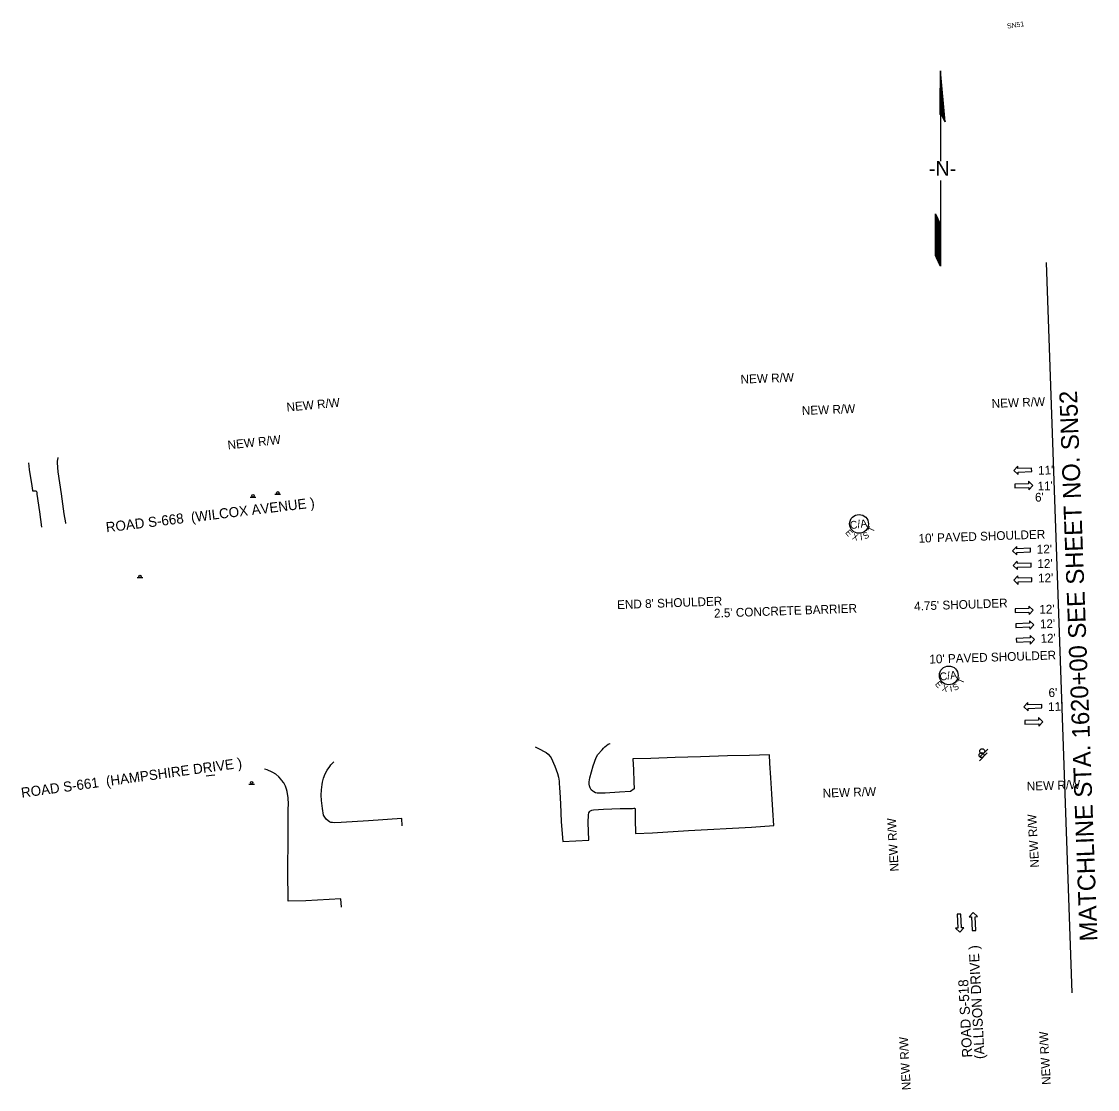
# Model space of a CAD drawing. Extents: x 1807400 to 1809002, y 1189416 to 1190516.
# Drawn here: x 1808144 to 1809002, y 1189664 to 1190516 of the extents above; entities that cross this region are included whole.
import ezdxf

# ---------------------------------------------------------------- set-up
doc = ezdxf.new("R2010")
doc.units = 0
for name, color, linetype in [('RD_EX_Road', 7, 'Continuous'), ('RD_PD_Final_LnLine', 7, 'Continuous'), ('RD_PD_Final_TX', 7, 'Continuous'), ('RD_PD_RW_TX', 7, 'Continuous'), ('RD_SHT_MatchLine', 7, 'Continuous'), ('RD_SHT_TX', 7, 'Continuous'), ('RD_Sketch1', 7, 'Continuous'), ('RD_Sketch8', 7, 'Continuous'), ('RD_TX_RoadID', 7, 'Continuous'), ('SN_P_Signs', 7, 'Continuous')]:
    doc.layers.add(name, color=color, linetype=linetype)

# ---------------------------------------------------------------- blocks, each defined once
blk = doc.blocks.new('SARRW2')
at = {"layer": 'RD_PD_Final_LnLine'}
blk.add_lwpolyline([(-12, 1.2), (-12, -1.2), (-2.83, -1.2), (-2.83, -2.83), (0, 0), (-2.83, 2.83), (-2.83, 1.2)], close=True, dxfattribs=at)

msp = doc.modelspace()

# ---------------------------------------------------------------- linework, layer by layer
at = {"layer": 'RD_EX_Road'}
for points in [[(1808160.15, 1190112.97), (1808158.56, 1190125.05), (1808156.51, 1190139.18), (1808156.33, 1190140.46), (1808156.04, 1190141.13), (1808155.62, 1190141.46), (1808155.39, 1190141.54), (1808154.94, 1190141.57), (1808154.67, 1190141.6), (1808154.21, 1190141.61), (1808153.42, 1190141.63), (1808152.99, 1190141.64), (1808152.87, 1190142.04), (1808152.31, 1190145.84), (1808150.36, 1190159), (1808149.69, 1190164.21)], [(1808179.38, 1190115.85), (1808179.29, 1190116.06), (1808179.19, 1190116.4), (1808177.84, 1190123.51), (1808175.71, 1190139.55), (1808173.13, 1190157.12), (1808172.49, 1190164.12), (1808172.65, 1190165.43), (1808172.72, 1190165.93), (1808172.87, 1190166.46), (1808172.94, 1190166.89), (1808173, 1190167.3), (1808173.04, 1190167.94), (1808173.04, 1190168.58)], [(1808553.71, 1189937.58), (1808558, 1189935.38), (1808560.49, 1189934.01), (1808562.46, 1189932.97), (1808564.21, 1189931.6), (1808565.69, 1189929.95), (1808566.44, 1189928.84), (1808569.35, 1189922.01), (1808570.4, 1189919.27), (1808571.62, 1189916.37), (1808572.46, 1189913.33), (1808572.92, 1189910.22), (1808573, 1189908.63), (1808573.21, 1189904.87), (1808573.55, 1189901.39), (1808573.94, 1189891.93), (1808574.41, 1189877.55), (1808575.84, 1189862.11), (1808596.65, 1189862.96), (1808596.05, 1189877.2), (1808596.3, 1189883.35), (1808596.64, 1189884.9), (1808597.01, 1189885.69), (1808597.37, 1189886.13), (1808597.83, 1189886.46), (1808599.06, 1189886.89), (1808600.37, 1189887.15), (1808608.26, 1189887.7), (1808621.65, 1189888.22), (1808631.53, 1189888.38), (1808632.51, 1189888.46), (1808632.99, 1189888.46), (1808633.39, 1189888.44), (1808633.57, 1189888.4), (1808633.67, 1189888.17), (1808633.46, 1189885.04), (1808633.52, 1189879.82), (1808633.95, 1189868.4), (1808647.46, 1189868.97), (1808676.11, 1189870.63), (1808726.27, 1189873.52), (1808744.3, 1189874.68), (1808743.36, 1189887), (1808742.57, 1189899.94), (1808741.71, 1189912.86), (1808740.98, 1189924.51), (1808740.65, 1189931.23), (1808724.9, 1189930.66), (1808707.17, 1189930.25), (1808685.64, 1189929.62), (1808665.59, 1189928.89), (1808646, 1189928.28), (1808631.8, 1189927.91), (1808632.18, 1189919.1), (1808632.48, 1189909.71), (1808632.66, 1189904.06), (1808629.73, 1189901.77), (1808621.16, 1189901.22), (1808609.52, 1189900.53), (1808604.82, 1189900.54), (1808603.29, 1189900.5), (1808601.79, 1189900.84), (1808600.44, 1189901.56), (1808599.78, 1189902.1), (1808598.54, 1189903.3), (1808597.59, 1189904.76), (1808597, 1189906.39), (1808596.81, 1189907.76), (1808596.84, 1189909.65), (1808597.44, 1189912.73), (1808599.99, 1189922.41), (1808602.47, 1189929.13), (1808603.77, 1189931.43), (1808607.28, 1189935.16), (1808608.28, 1189936.47), (1808609.42, 1189937.66), (1808610.7, 1189938.69), (1808612.09, 1189939.57), (1808613.58, 1189940.28), (1808613.65, 1189940.31)], [(1808447.69, 1189874.41), (1808447.37, 1189880.31), (1808420.81, 1189878.37), (1808398.86, 1189877.26), (1808393.62, 1189877), (1808392.06, 1189877.04), (1808390.72, 1189877.17), (1808389.6, 1189877.6), (1808388.61, 1189878.39), (1808387.09, 1189879.81), (1808385.94, 1189881.29), (1808384.97, 1189883.05), (1808383.96, 1189888.29), (1808383.24, 1189894.79), (1808382.99, 1189899.04), (1808383.14, 1189903.3), (1808383.68, 1189907.53), (1808384, 1189909.22), (1808384.92, 1189912.6), (1808386.2, 1189915.87), (1808387.85, 1189918.97), (1808389.83, 1189921.86), (1808390.83, 1189923.1), (1808392.51, 1189924.99), (1808393.12, 1189925.48)], [(1808298.08, 1189915.01), (1808295.53, 1189914.65), (1808291.36, 1189914.18)], [(1808399.22, 1189809.6), (1808398.8, 1189816.17), (1808370.69, 1189814.73), (1808356.57, 1189814.25), (1808356.49, 1189838.68), (1808356.55, 1189864.58), (1808356.77, 1189877.24), (1808356.79, 1189887.82), (1808356.85, 1189891.81), (1808356.58, 1189896.85), (1808355.91, 1189901.86), (1808355.47, 1189903.63), (1808354.48, 1189906.27), (1808353.12, 1189908.74), (1808351.44, 1189911), (1808351.03, 1189911.56), (1808349.1, 1189913.72), (1808346.9, 1189915.61), (1808344.46, 1189917.17), (1808343.91, 1189917.43), (1808339.95, 1189919.06), (1808337.87, 1189919.7)]]:
    msp.add_lwpolyline(points, dxfattribs=at)
at = {"layer": 'RD_SHT_MatchLine'}
msp.add_line((1808961.42, 1190323.98), (1808981.96, 1189741.27), dxfattribs=at)
at = {"layer": 'RD_Sketch1'}
for p, q in [((1808877.06, 1190477.18), (1808876.85, 1190442.01)), ((1808880.79, 1190436.48), (1808877.06, 1190477.18)), ((1808877.06, 1190442.31), (1808877.06, 1190420.49)), ((1808877.37, 1190443.42), (1808880.79, 1190436.48)), ((1808877.06, 1190420.49), (1808877.06, 1190405.01)), ((1808877.06, 1190389.57), (1808877.06, 1190363.79)), ((1808873.07, 1190348.74), (1808873.07, 1190362.91)), ((1808873.07, 1190362.91), (1808877.06, 1190354.34)), ((1808877.06, 1190363.79), (1808877.06, 1190321.27)), ((1808873.07, 1190329.84), (1808873.07, 1190348.74)), ((1808877.06, 1190321.27), (1808873.07, 1190329.84))]:
    msp.add_line(p, q, dxfattribs=at)
for points in [[(1808877.07, 1190442.62), (1808877.07, 1190477.06)], [(1808877.17, 1190442.88), (1808877.17, 1190476.03)], [(1808877.26, 1190443.14), (1808877.26, 1190474.99)], [(1808877.36, 1190443.4), (1808877.36, 1190473.96)], [(1808877.45, 1190443.24), (1808877.45, 1190472.93)], [(1808877.55, 1190443.05), (1808877.55, 1190471.9)], [(1808877.64, 1190442.86), (1808877.64, 1190470.86)], [(1808877.74, 1190442.67), (1808877.74, 1190469.83)], [(1808877.83, 1190442.48), (1808877.83, 1190468.8)], [(1808877.92, 1190442.29), (1808877.92, 1190467.77)], [(1808878.02, 1190442.09), (1808878.02, 1190466.73)], [(1808878.11, 1190441.9), (1808878.11, 1190465.7)], [(1808878.21, 1190441.71), (1808878.21, 1190464.67)], [(1808876.98, 1190442.36), (1808876.98, 1190463.14)], [(1808878.3, 1190441.52), (1808878.3, 1190463.64)], [(1808878.4, 1190441.33), (1808878.4, 1190462.6)], [(1808878.49, 1190441.14), (1808878.49, 1190461.57)], [(1808878.59, 1190440.94), (1808878.59, 1190460.54)], [(1808878.68, 1190440.75), (1808878.68, 1190459.51)], [(1808878.77, 1190440.56), (1808878.77, 1190458.47)], [(1808878.87, 1190440.37), (1808878.87, 1190457.44)], [(1808878.96, 1190440.18), (1808878.96, 1190456.41)], [(1808879.06, 1190439.99), (1808879.06, 1190455.38)], [(1808876.88, 1190442.1), (1808876.88, 1190447.24)], [(1808879.15, 1190439.79), (1808879.15, 1190454.34)], [(1808879.25, 1190439.6), (1808879.25, 1190453.31)], [(1808879.34, 1190439.41), (1808879.34, 1190452.28)], [(1808879.44, 1190439.22), (1808879.44, 1190451.25)], [(1808879.53, 1190439.03), (1808879.53, 1190450.21)], [(1808879.62, 1190438.84), (1808879.62, 1190449.18)], [(1808879.72, 1190438.64), (1808879.72, 1190448.15)], [(1808879.81, 1190438.45), (1808879.81, 1190447.12)], [(1808879.91, 1190438.26), (1808879.91, 1190446.08)], [(1808880, 1190438.07), (1808880, 1190445.05)], [(1808880.1, 1190437.88), (1808880.1, 1190444.02)], [(1808880.19, 1190437.68), (1808880.19, 1190442.99)], [(1808880.29, 1190437.49), (1808880.29, 1190441.95)], [(1808880.38, 1190437.3), (1808880.38, 1190440.92)], [(1808880.48, 1190437.11), (1808880.48, 1190439.89)], [(1808880.57, 1190436.92), (1808880.57, 1190438.86)], [(1808880.66, 1190436.73), (1808880.66, 1190437.82)], [(1808880.76, 1190436.53), (1808880.76, 1190436.79)], [(1808873.15, 1190329.67), (1808873.15, 1190362.74)], [(1808873.24, 1190329.47), (1808873.24, 1190362.54)], [(1808873.34, 1190329.27), (1808873.34, 1190362.34)], [(1808873.43, 1190329.06), (1808873.43, 1190362.14)], [(1808873.52, 1190328.86), (1808873.52, 1190361.93)], [(1808873.62, 1190328.66), (1808873.62, 1190361.73)], [(1808873.71, 1190328.46), (1808873.71, 1190361.53)], [(1808873.81, 1190328.25), (1808873.81, 1190361.32)], [(1808873.9, 1190328.05), (1808873.9, 1190361.12)], [(1808874, 1190327.85), (1808874, 1190360.92)], [(1808874.09, 1190327.65), (1808874.09, 1190360.72)], [(1808874.19, 1190327.44), (1808874.19, 1190360.51)], [(1808874.28, 1190327.24), (1808874.28, 1190360.31)], [(1808874.37, 1190327.04), (1808874.37, 1190360.11)], [(1808874.47, 1190326.84), (1808874.47, 1190359.91)], [(1808874.56, 1190326.63), (1808874.56, 1190359.7)], [(1808874.66, 1190326.43), (1808874.66, 1190359.5)], [(1808874.75, 1190326.23), (1808874.75, 1190359.3)], [(1808874.85, 1190326.03), (1808874.85, 1190359.1)], [(1808874.94, 1190325.82), (1808874.94, 1190358.89)], [(1808875.04, 1190325.62), (1808875.04, 1190358.69)], [(1808875.13, 1190325.42), (1808875.13, 1190358.49)], [(1808875.23, 1190325.21), (1808875.23, 1190358.29)], [(1808875.32, 1190325.01), (1808875.32, 1190358.08)], [(1808875.41, 1190324.81), (1808875.41, 1190357.88)], [(1808875.51, 1190324.61), (1808875.51, 1190357.68)], [(1808875.6, 1190324.4), (1808875.6, 1190357.47)], [(1808875.7, 1190324.2), (1808875.7, 1190357.27)], [(1808875.79, 1190324), (1808875.79, 1190357.07)], [(1808875.89, 1190323.8), (1808875.89, 1190356.87)], [(1808875.98, 1190323.59), (1808875.98, 1190356.66)], [(1808876.08, 1190323.39), (1808876.08, 1190356.46)], [(1808876.17, 1190323.19), (1808876.17, 1190356.26)], [(1808876.26, 1190322.99), (1808876.26, 1190356.06)], [(1808876.36, 1190322.78), (1808876.36, 1190355.85)], [(1808876.45, 1190322.58), (1808876.45, 1190355.65)], [(1808876.55, 1190322.38), (1808876.55, 1190355.45)], [(1808876.64, 1190322.18), (1808876.64, 1190355.25)], [(1808876.74, 1190321.97), (1808876.74, 1190355.04)], [(1808876.83, 1190321.77), (1808876.83, 1190354.84)], [(1808876.93, 1190321.57), (1808876.93, 1190354.64)], [(1808877.02, 1190321.36), (1808877.02, 1190354.44)]]:
    msp.add_lwpolyline(points, dxfattribs=at)
at = {"layer": 'RD_Sketch8'}
for centre in [(1808812.19, 1190115.46), (1808883.78, 1189994.54)]:
    msp.add_circle(centre, 7.5, dxfattribs=at)
at = {"layer": 'SN_P_Signs'}
for p, q in [((1808346.13, 1190139.2), (1808350.63, 1190139.2)), ((1808326.32, 1190136.89), (1808330.82, 1190136.89)), ((1808236.16, 1190072.6), (1808240.66, 1190072.6)), ((1808908.18, 1189926.28), (1808914.54, 1189932.65)), ((1808908.69, 1189929.42), (1808915.05, 1189935.78)), ((1808325.26, 1189907.85), (1808329.76, 1189907.85))]:
    msp.add_line(p, q, dxfattribs=at)
for centre, radius in [((1808328.58, 1190137.9), 1), ((1808348.39, 1190140.21), 1), ((1808238.42, 1190073.61), 1), ((1808909.94, 1189930.91), 2), ((1808910.45, 1189934.05), 2), ((1808327.52, 1189908.86), 1)]:
    msp.add_circle(centre, radius, dxfattribs=at)

# ---------------------------------------------------------------- block references
at = {"layer": 'RD_PD_Final_LnLine', "yscale": 1.2000000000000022}
for p, xscale, rotation in [((1808935.59, 1190158.11), 1.1999999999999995, -177.9816202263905), ((1808950.9, 1190146.18), 1.1999999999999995, 2.018379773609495), ((1808934.69, 1190094.03), 1.1999999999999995, -177.9816202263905), ((1808935.19, 1190082.25), 1.1999999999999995, -177.9816202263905), ((1808935.69, 1190070.47), 1.1999999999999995, -177.9816202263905), ((1808951.13, 1190046.63), 1.1999999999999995, 2.018379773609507), ((1808951.63, 1190034.85), 1.1999999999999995, 2.018379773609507), ((1808952.13, 1190023.08), 1.1999999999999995, 2.018379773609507), ((1808943.61, 1189969.49), 1.1999999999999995, -177.9816202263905), ((1808958.92, 1189957.56), 1.1999999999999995, 2.018379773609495), ((1808892.54, 1189789.53), 1.1999999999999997, -87.98162022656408), ((1808903.32, 1189805.28), 1.1999999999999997, 92.01837977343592)]:
    msp.add_blockref('SARRW2', p, dxfattribs=dict(at, xscale=xscale, rotation=rotation))

# ---------------------------------------------------------------- texts
at = {"layer": 'RD_PD_Final_TX'}
for s, rotation, p in [("11'", 1.39156, (1808955.1, 1190154.71)), ("11'", 1.39156, (1808954.69, 1190142.13)), ("6'", 1.69659, (1808952.72, 1190133.17)), ("10' PAVED SHOULDER", 1.90447, (1808859.76, 1190100.44)), ("12'", 1.39156, (1808954.06, 1190091.7)), ("12'", 1.39156, (1808954.55, 1190080.19)), ("12'", 1.39156, (1808955.04, 1190068.67)), ("END 8' SHOULDER", 2.02288, (1808619.23, 1190047.44)), ("4.75' SHOULDER", 2.01838, (1808856.26, 1190046.28)), ("2.5' CONCRETE BARRIER", 2.02012, (1808696.6, 1190040.64)), ("12'", 1.39156, (1808956.1, 1190043.7)), ("12'", 1.39156, (1808956.59, 1190032.12)), ("12'", 1.39156, (1808957.08, 1190020.53)), ("10' PAVED SHOULDER", 1.90447, (1808868.42, 1190003.95)), ("6'", 1.69659, (1808963.47, 1189977.22)), ("11'", 1.39156, (1808963.11, 1189966.09))]:
    msp.add_text(s, height=7, rotation=rotation, dxfattribs=at).set_placement(p)
at = {"layer": 'RD_PD_RW_TX'}
for rotation, p in [(2.19362, (1808717.75, 1190227.39)), (5.40114, (1808355.7, 1190205.06)), (2.19362, (1808918.12, 1190208.01)), (2.19362, (1808766.65, 1190202.38)), (6.16423, (1808308.7, 1190174.88)), (1.89303, (1808946.13, 1189902.56)), (1.89303, (1808783.27, 1189897.04)), (93.16755, (1808843.92, 1189838.24)), (93.16755, (1808955.92, 1189841.33)), (93.16755, (1808965.24, 1189667.96)), (93.16755, (1808853.52, 1189663.68))]:
    msp.add_text('NEW R/W', height=7, rotation=rotation, dxfattribs=at).set_placement(p)
at = {"layer": 'RD_SHT_TX'}
for s, height, rotation, p in [('SN51', 4, 8.10669, (1808930.53, 1190510.74)), ('MATCHLINE STA. 1620+00 SEE SHEET NO. SN52', 14.1726, 92.14236, (1809002.51, 1189782.58))]:
    msp.add_text(s, height=height, rotation=rotation, dxfattribs=at).set_placement(p)
at = {"layer": 'RD_Sketch1'}
msp.add_text('-N-', height=11.811, rotation=0, dxfattribs=at).set_placement((1808867.87, 1190393.28))
at = {"layer": 'RD_Sketch8'}
for s, height, rotation, p in [('C/A', 6.25, 8.10669, (1808805.31, 1190111.17)), ('T', 5, 66.29183, (1808823.5, 1190108.27)), ('E', 5, 311.31793, (1808800.87, 1190108.27)), ('X', 5, 343.7473, (1808806.4, 1190103.34)), ('I', 5, 7.9073, (1808813.4, 1190102.25)), ('S', 5, 29.89913, (1808816.99, 1190102.94)), ('C/A', 6.25, 8.10669, (1808876.9, 1189990.25)), ('T', 5, 66.29183, (1808895.09, 1189987.36)), ('E', 5, 311.31793, (1808872.46, 1189987.36)), ('X', 5, 343.7473, (1808877.99, 1189982.43)), ('I', 5, 7.9073, (1808884.99, 1189981.34)), ('S', 5, 29.89913, (1808888.58, 1189982.02))]:
    msp.add_text(s, height=height, rotation=rotation, dxfattribs=at).set_placement(p)
at = {"layer": 'RD_TX_RoadID'}
for s, rotation, p in [('ROAD S-668  (WILCOX AVENUE )', 6.81683, (1808211.69, 1190108.72)), ('ROAD S-661  (HAMPSHIRE DRIVE )', 7.76462, (1808144.11, 1189896.88)), ('(ALLISON DRIVE )', 93.04789, (1808912.43, 1189688.54)), ('ROAD S-518', 93.04789, (1808902.56, 1189689.79))]:
    msp.add_text(s, height=8, rotation=rotation, dxfattribs=at).set_placement(p)

doc.saveas('drawing.dxf')
